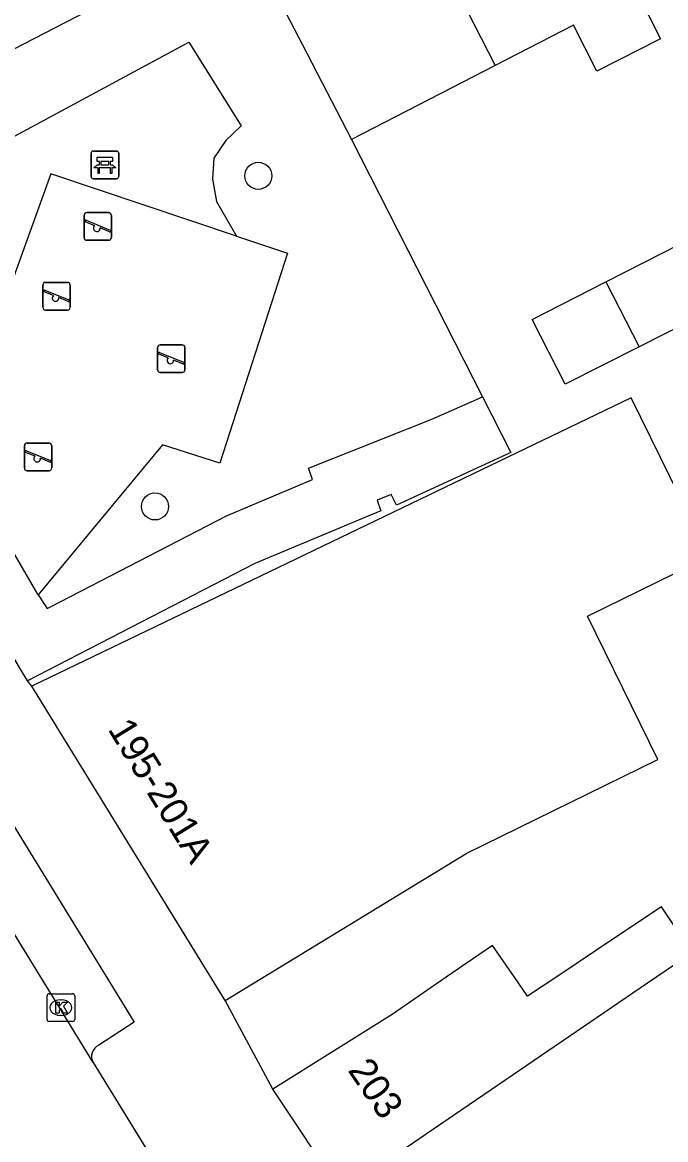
# Model space of a CAD drawing. Extents: x 159888 to 160757, y 384031 to 384746.
# Drawn here: x 160543.3 to 160566.56, y 384244.13 to 384284.54 of the extents above; entities that cross this region are included whole.
import ezdxf

# ---------------------------------------------------------------- set-up
doc = ezdxf.new("R2010")
doc.units = 0
for name, color, linetype in [('IMGEO_Bank', 7, 'Continuous'), ('IMGEO_Boom', 7, 'Continuous'), ('IMGEO_Groenvoorziening', 7, 'Continuous'), ('IMGEO_Kolk', 7, 'Continuous'), ('IMGEO_Pand', 7, 'Continuous'), ('IMGEO_Pand_nummerreeks', 7, 'Continuous'), ('IMGEO_Rijbaan_lokaal_open', 7, 'Continuous'), ('IMGEO_Speelvoorziening', 7, 'Continuous'), ('IMGEO_Voetpad_open', 7, 'Continuous')]:
    doc.layers.add(name, color=color, linetype=linetype)

msp = doc.modelspace()

# ---------------------------------------------------------------- linework, layer by layer
at = {"layer": 'IMGEO_Bank'}
for p, q in [((160545.855, 384279.884), (160546.696, 384279.884)), ((160546.696, 384279.884), (160545.855, 384279.884)), ((160545.78, 384278.959), (160545.78, 384279.8)), ((160545.78, 384279.8), (160545.78, 384278.959)), ((160546.089, 384279.39), (160546.089, 384279.496)), ((160546.133, 384279.496), (160546.133, 384279.39)), ((160546.421, 384279.502), (160546.139, 384279.502)), ((160546.427, 384279.39), (160546.427, 384279.496)), ((160546.471, 384279.496), (160546.471, 384279.39)), ((160546.78, 384279.809), (160546.78, 384278.968)), ((160546.78, 384278.968), (160546.78, 384279.809)), ((160546.477, 384279.282), (160546.084, 384279.282)), ((160546.139, 384279.384), (160546.421, 384279.384)), ((160546.705, 384278.884), (160545.864, 384278.884)), ((160545.864, 384278.884), (160546.705, 384278.884))]:
    msp.add_line(p, q, dxfattribs=at)
for points in [[(160546.083, 384279.502), (160545.997, 384279.502), (160545.997, 384279.663), (160546.56, 384279.663), (160546.56, 384279.502), (160546.477, 384279.502)], [(160546.027, 384279.282), (160545.885, 384279.282), (160545.997, 384279.384), (160546.083, 384279.384)], [(160546.077, 384279.275), (160546.077, 384279.068), (160546.034, 384279.068), (160546.034, 384279.275)], [(160546.477, 384279.384), (160546.56, 384279.384), (160546.672, 384279.282), (160546.533, 384279.282)], [(160546.527, 384279.275), (160546.527, 384279.068), (160546.483, 384279.068), (160546.483, 384279.275)]]:
    msp.add_lwpolyline(points, dxfattribs=at)
for centre, radius, start, end in [((160545.858, 384279.806), 0.0779, 92.4484, 184.2845), ((160545.858, 384279.806), 0.0779, 92.4484, 184.2845), ((160546.702, 384279.806), 0.0779, 2.4484, 94.2845), ((160546.702, 384279.806), 0.0779, 2.4484, 94.2845), ((160546.082, 384279.495), 0.00671, 2.8957, 87.1043), ((160546.139, 384279.495), 0.00671, 92.8957, 177.1043), ((160546.421, 384279.495), 0.00671, 2.8957, 87.1043), ((160546.478, 384279.495), 0.00671, 92.8957, 177.1043), ((160546.027, 384279.275), 0.00671, 2.8957, 87.1043), ((160546.084, 384279.275), 0.00671, 92.8957, 177.1043), ((160546.082, 384279.391), 0.00671, 272.8957, 357.1043), ((160546.139, 384279.391), 0.00671, 182.8957, 267.1043), ((160546.421, 384279.391), 0.00671, 272.8957, 357.1043), ((160546.478, 384279.391), 0.00671, 182.8957, 267.1043), ((160546.476, 384279.275), 0.00671, 2.8957, 87.1043), ((160546.533, 384279.275), 0.00671, 92.8957, 177.1043), ((160545.858, 384278.962), 0.0779, 182.4484, 274.2845), ((160545.858, 384278.962), 0.0779, 182.4484, 274.2845), ((160546.702, 384278.962), 0.0779, 272.4484, 4.2845), ((160546.702, 384278.962), 0.0779, 272.4484, 4.2845)]:
    msp.add_arc(centre, radius, start, end, dxfattribs=at)
at = {"layer": 'IMGEO_Boom'}
for centre in [(160551.829, 384278.987), (160548.093, 384267.029)]:
    msp.add_circle(centre, 0.489, dxfattribs=at)
at = {"layer": 'IMGEO_Groenvoorziening'}
for points in [[(160536.442, 384278.002), (160537.944, 384277.697), (160549.322, 384283.817), (160551.212, 384280.795), (160550.654, 384280.266), (160550.225, 384279.629), (160550.169, 384278.862), (160550.319, 384278.053), (160551.037, 384276.806)], [(160555.203, 384280.304), (160559.938, 384270.993)], [(160551.037, 384276.806), (160544.321, 384279.062), (160540.748, 384269.155)], [(160551.037, 384276.806), (160552.885, 384276.185), (160550.436, 384268.6), (160548.359, 384269.253), (160543.871, 384263.833)], [(160559.938, 384270.993), (160560.964, 384268.976), (160556.833, 384267.08), (160556.642, 384267.456), (160556.135, 384267.254), (160556.26, 384266.871), (160551.702, 384264.96), (160543.477, 384260.72)], [(160543.871, 384263.833), (160544.188, 384263.332), (160544.342, 384263.416), (160550.681, 384266.684), (160553.787, 384268.003), (160553.651, 384268.417), (160558.102, 384270.191), (160559.938, 384270.993)], [(160543.871, 384263.833), (160541.766, 384267.42), (160540.748, 384269.155)]]:
    msp.add_lwpolyline(points, dxfattribs=at)
at = {"layer": 'IMGEO_Kolk'}
for p, q in [((160544.188, 384248.476), (160544.188, 384249.328)), ((160544.263, 384249.402), (160545.115, 384249.402)), ((160544.676, 384249.182), (160544.701, 384249.182)), ((160545.189, 384249.328), (160545.189, 384248.476)), ((160545.115, 384248.402), (160544.263, 384248.402)), ((160544.699, 384248.622), (160544.674, 384248.622))]:
    msp.add_line(p, q, dxfattribs=at)
for points in [[(160544.188, 384248.476), (160544.188, 384249.328)], [(160544.263, 384249.402), (160545.115, 384249.402)], [(160545.189, 384249.328), (160545.189, 384248.476)], [(160544.509, 384249.102), (160544.632, 384249.102), (160544.632, 384248.951), (160544.762, 384249.102), (160544.926, 384249.102), (160544.78, 384248.951), (160544.933, 384248.702), (160544.781, 384248.702), (160544.696, 384248.866), (160544.632, 384248.799), (160544.632, 384248.702), (160544.509, 384248.702), (160544.509, 384249.102)], [(160545.115, 384248.402), (160544.263, 384248.402)]]:
    msp.add_lwpolyline(points, dxfattribs=at)
for centre, start, end in [((160544.265, 384249.326), 91.552, 178.448), ((160544.265, 384249.326), 91.552, 178.448), ((160545.113, 384249.326), 1.552, 88.448), ((160545.113, 384249.326), 1.552, 88.448), ((160544.265, 384248.478), 181.552, 268.448), ((160544.265, 384248.478), 181.552, 268.448), ((160545.113, 384248.478), 271.552, 358.448), ((160545.113, 384248.478), 271.552, 358.448)]:
    msp.add_arc(centre, 0.0765, start, end, dxfattribs=at)
for centre, major_axis, ratio, start_param, end_param in [((160544.675, 384248.902), (-0.387, 0.002), 0.722429, 4.712389, 7.853982), ((160544.7, 384248.902), (-0.39, 0.002), 0.717154, 1.570796, 4.712389)]:
    msp.add_ellipse(centre, major_axis=major_axis, ratio=ratio, start_param=start_param, end_param=end_param, dxfattribs=at)
at = {"layer": 'IMGEO_Pand'}
for points in [[(160556.531, 384290.55), (160560.401, 384282.978)], [(160551.279, 384287.856), (160553.584, 384283.42), (160555.203, 384280.304)], [(160565.536, 384285.62), (160566.384, 384283.945), (160564.075, 384282.776), (160563.235, 384284.436), (160560.401, 384282.978)], [(160560.401, 384282.978), (160555.203, 384280.304)], [(160564.401, 384275.151), (160567.097, 384276.524), (160568.297, 384274.167), (160565.602, 384272.802)], [(160565.602, 384272.802), (160562.925, 384271.446), (160561.74, 384273.796), (160564.401, 384275.151)], [(160564.401, 384275.151), (160565.602, 384272.802)], [(160550.637, 384249.155), (160559.369, 384254.49), (160566.28, 384257.873), (160563.733, 384263.06), (160568.138, 384265.216), (160565.32, 384270.954), (160543.642, 384260.525)], [(160550.637, 384249.155), (160543.642, 384260.525)], [(160567.525, 384250.9), (160566.42, 384252.548), (160564.767, 384251.446), (160562.59, 384249.994), (160561.569, 384249.314), (160561.097, 384250), (160560.302, 384251.154), (160558.63, 384250), (160556.673, 384248.649), (160552.352, 384245.954)], [(160554.829, 384242.238), (160565.911, 384249.799), (160567.525, 384250.9)], [(160554.829, 384242.238), (160552.352, 384245.954)]]:
    msp.add_lwpolyline(points, dxfattribs=at)
at = {"layer": 'IMGEO_Rijbaan_lokaal_open'}
for points in [[(160545.852, 384246.914), (160538, 384259.726), (160530.263, 384272.354)], [(160545.852, 384246.914), (160549.185, 384241.499)]]:
    msp.add_lwpolyline(points, dxfattribs=at)
at = {"layer": 'IMGEO_Speelvoorziening'}
for p, q in [((160545.529, 384276.755), (160545.529, 384277.555)), ((160545.529, 384277.555), (160545.529, 384276.755)), ((160545.629, 384277.655), (160546.419, 384277.655)), ((160546.419, 384277.655), (160545.629, 384277.655)), ((160546.519, 384277.555), (160546.519, 384276.755)), ((160546.519, 384276.755), (160546.519, 384277.555)), ((160545.912, 384277.183), (160545.573, 384277.32)), ((160545.598, 384277.38), (160546.474, 384277.027)), ((160546.45, 384276.967), (160546.11, 384277.104)), ((160546.419, 384276.655), (160545.629, 384276.655)), ((160545.629, 384276.655), (160546.419, 384276.655)), ((160544.035, 384274.232), (160544.035, 384275.032)), ((160544.035, 384275.032), (160544.035, 384274.232)), ((160544.135, 384275.132), (160544.925, 384275.132)), ((160544.925, 384275.132), (160544.135, 384275.132)), ((160545.025, 384275.032), (160545.025, 384274.232)), ((160545.025, 384274.232), (160545.025, 384275.032)), ((160544.418, 384274.66), (160544.079, 384274.797)), ((160544.104, 384274.857), (160544.98, 384274.504)), ((160544.956, 384274.444), (160544.616, 384274.581)), ((160544.925, 384274.132), (160544.135, 384274.132)), ((160544.135, 384274.132), (160544.925, 384274.132)), ((160548.185, 384271.974), (160548.185, 384272.774)), ((160548.185, 384272.774), (160548.185, 384271.974)), ((160548.254, 384272.599), (160549.13, 384272.246)), ((160548.285, 384272.874), (160549.075, 384272.874)), ((160549.075, 384272.874), (160548.285, 384272.874)), ((160549.175, 384272.774), (160549.175, 384271.974)), ((160549.175, 384271.974), (160549.175, 384272.774)), ((160548.568, 384272.402), (160548.229, 384272.539)), ((160549.106, 384272.186), (160548.766, 384272.323)), ((160549.075, 384271.874), (160548.285, 384271.874)), ((160548.285, 384271.874), (160549.075, 384271.874)), ((160543.371, 384268.421), (160543.371, 384269.221)), ((160543.371, 384269.221), (160543.371, 384268.421)), ((160543.754, 384268.849), (160543.415, 384268.986)), ((160543.44, 384269.046), (160544.316, 384268.693)), ((160543.471, 384269.321), (160544.261, 384269.321)), ((160544.261, 384269.321), (160543.471, 384269.321)), ((160544.361, 384269.221), (160544.361, 384268.421)), ((160544.361, 384268.421), (160544.361, 384269.221)), ((160544.292, 384268.633), (160543.952, 384268.77)), ((160544.261, 384268.321), (160543.471, 384268.321)), ((160543.471, 384268.321), (160544.261, 384268.321))]:
    msp.add_line(p, q, dxfattribs=at)
for centre, radius, start, end in [((160545.629, 384277.555), 0.1, 90, 180), ((160545.629, 384277.555), 0.1, 90, 180), ((160546.419, 384277.555), 0.1, 0, 90), ((160546.419, 384277.555), 0.1, 360, 90), ((160545.586, 384277.35), 0.0327, 68.078, 248.078), ((160545.991, 384277.093), 0.12, 130.9928, 5.1632), ((160545.629, 384276.755), 0.1, 180, 270), ((160545.629, 384276.755), 0.1, 180, 270), ((160546.419, 384276.755), 0.1, 270, 0), ((160546.419, 384276.755), 0.1, 270, 0), ((160546.462, 384276.997), 0.0327, 248.078, 68.078), ((160544.135, 384275.032), 0.1, 90, 180), ((160544.135, 384275.032), 0.1, 90, 180), ((160544.925, 384275.032), 0.1, 0, 90), ((160544.925, 384275.032), 0.1, 360, 90), ((160544.092, 384274.827), 0.0327, 68.078, 248.078), ((160544.497, 384274.57), 0.12, 130.9928, 5.1632), ((160544.135, 384274.232), 0.1, 180, 270), ((160544.135, 384274.232), 0.1, 180, 270), ((160544.925, 384274.232), 0.1, 270, 0), ((160544.925, 384274.232), 0.1, 270, 0), ((160544.968, 384274.474), 0.0327, 248.078, 68.078), ((160548.285, 384272.774), 0.1, 90, 180), ((160548.285, 384272.774), 0.1, 90, 180), ((160548.242, 384272.569), 0.0327, 68.078, 248.078), ((160549.075, 384272.774), 0.1, 0, 90), ((160549.075, 384272.774), 0.1, 360, 90), ((160548.647, 384272.312), 0.12, 130.9928, 5.1632), ((160549.118, 384272.216), 0.0327, 248.078, 68.078), ((160548.285, 384271.974), 0.1, 180, 270), ((160548.285, 384271.974), 0.1, 180, 270), ((160549.075, 384271.974), 0.1, 270, 0), ((160549.075, 384271.974), 0.1, 270, 0), ((160543.471, 384269.221), 0.1, 90, 180), ((160543.471, 384269.221), 0.1, 90, 180), ((160543.428, 384269.016), 0.0327, 68.078, 248.078), ((160544.261, 384269.221), 0.1, 0, 90), ((160544.261, 384269.221), 0.1, 360, 90), ((160543.833, 384268.759), 0.12, 130.9928, 5.1632), ((160544.304, 384268.663), 0.0327, 248.078, 68.078), ((160543.471, 384268.421), 0.1, 180, 270), ((160543.471, 384268.421), 0.1, 180, 270), ((160544.261, 384268.421), 0.1, 270, 0), ((160544.261, 384268.421), 0.1, 270, 0)]:
    msp.add_arc(centre, radius, start, end, dxfattribs=at)
at = {"layer": 'IMGEO_Voetpad_open'}
for points in [[(160551.279, 384287.856), (160533.88, 384278.879)], [(160543.477, 384260.72), (160533.414, 384277.545)], [(160532.196, 384273.02), (160539.733, 384260.755), (160547.34, 384248.378), (160546.057, 384247.544)], [(160543.642, 384260.525), (160543.477, 384260.72)], [(160552.352, 384245.954), (160550.637, 384249.155)]]:
    msp.add_lwpolyline(points, dxfattribs=at)
msp.add_arc((160546.261, 384247.129), 0.462, 116.1611, 207.7895, dxfattribs=at)

# ---------------------------------------------------------------- texts
at = {"layer": 'IMGEO_Pand_nummerreeks'}
for s, rotation, p in [('195-201A', 301.6271, (160546.366, 384258.971)), ('203', 304.3314, (160555.046, 384246.633))]:
    msp.add_text(s, height=1, rotation=rotation, dxfattribs=at).set_placement(p)

doc.saveas('drawing.dxf')
